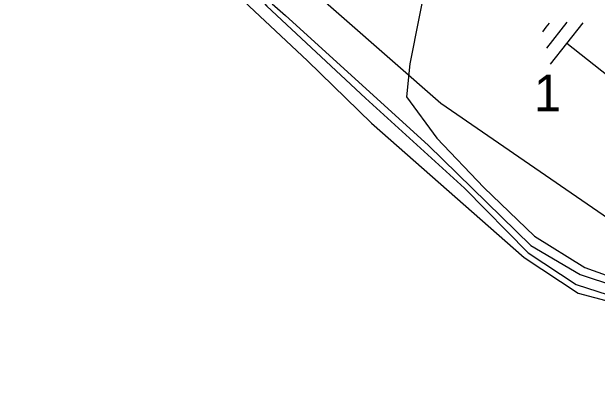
# Model space of a CAD drawing. Extents: x -540340 to -537226, y -1183949 to -1180375.
# Drawn here: x -537542.2 to -537514.32, y -1180689.97 to -1180671.08 of the extents above; entities that cross this region are included whole.
import ezdxf

# ---------------------------------------------------------------- set-up
doc = ezdxf.new("R2010")
doc.units = 0
for name, color, linetype in [('Vrstva 14', 7, 'Continuous'), ('Vrstva 15', 7, 'Continuous'), ('Vrstva 5', 7, 'Continuous')]:
    doc.layers.add(name, color=color, linetype=linetype)

msp = doc.modelspace()

# ---------------------------------------------------------------- linework, layer by layer
at = {"layer": 'Vrstva 15'}
for points in [[(-537516.743, -1180671.823), (-537516.584, -1180671.622)], [(-537516.724, -1180672.816), (-537515.748, -1180671.58)], [(-537516.536, -1180673.578), (-537514.987, -1180671.616)], [(-537516.907, -1180672.031), (-537516.743, -1180671.823)], [(-537513.8, -1180674.147), (-537515.762, -1180672.597)]]:
    msp.add_lwpolyline(points, dxfattribs=at)
at = {"layer": 'Vrstva 5'}
for points in [[(-537537.553, -1180656.912), (-537538.874, -1180656.367), (-537540.174, -1180656.342), (-537541.44, -1180656.898), (-537542.203, -1180658.073), (-537542.19, -1180659.42), (-537541.9, -1180660.457), (-537539.51, -1180662.628), (-537535.624, -1180665.351), (-537531.538, -1180669.106), (-537530.048, -1180670.81), (-537525.356, -1180675.203), (-537520.634, -1180679.488), (-537517.6, -1180682.56), (-537515.324, -1180684.078), (-537513.804, -1180684.574)], [(-537536.659, -1180657.565), (-537535.107, -1180658.402), (-537534.978, -1180659.35), (-537536.044, -1180661.779), (-537536.522, -1180663.622), (-537536.16, -1180665.522), (-537535.216, -1180666.749), (-537532.16, -1180669.611), (-537528.12, -1180673.417), (-537525.071, -1180676.392), (-537517.795, -1180682.792), (-537515.228, -1180684.492), (-537513.669, -1180684.903)], [(-537530.88, -1180661.777), (-537532.373, -1180661.319), (-537533.384, -1180662.138), (-537534.594, -1180663.747), (-537534.304, -1180664.462), (-537528.918, -1180669.148), (-537521.77, -1180675.432), (-537512.808, -1180681.594), (-537509.997, -1180683.987), (-537501.368, -1180690.23), (-537495.897, -1180693.015), (-537484.881, -1180695.744), (-537477.363, -1180695.954), (-537470.096, -1180697.063), (-537463.413, -1180697.101), (-537453.89, -1180696.053), (-537446.059, -1180695.542), (-537435.563, -1180695.142), (-537412.336, -1180694.313)], [(-537524.622, -1180666.267), (-537525.171, -1180665.347), (-537526.296, -1180664.853), (-537527.665, -1180665.525), (-537528.898, -1180667.527), (-537529.765, -1180669.565), (-537529.795, -1180670.7), (-537529.157, -1180671.263), (-537522.37, -1180677.438), (-537517.485, -1180682.211), (-537515.124, -1180683.606), (-537513.442, -1180684.149)], [(-537523.685, -1180666.914), (-537522.52, -1180668.268), (-537522.345, -1180668.988), (-537523.248, -1180673.562), (-537523.402, -1180675.142), (-537521.953, -1180677.098), (-537519.715, -1180679.454), (-537517.304, -1180681.781), (-537514.902, -1180683.27), (-537513.267, -1180683.855)]]:
    msp.add_lwpolyline(points, dxfattribs=at)

# ---------------------------------------------------------------- texts
at = {"layer": 'Vrstva 14'}
msp.add_text('1', height=1.75, dxfattribs=at).set_placement((-537517.336, -1180675.832))

doc.saveas('drawing.dxf')
